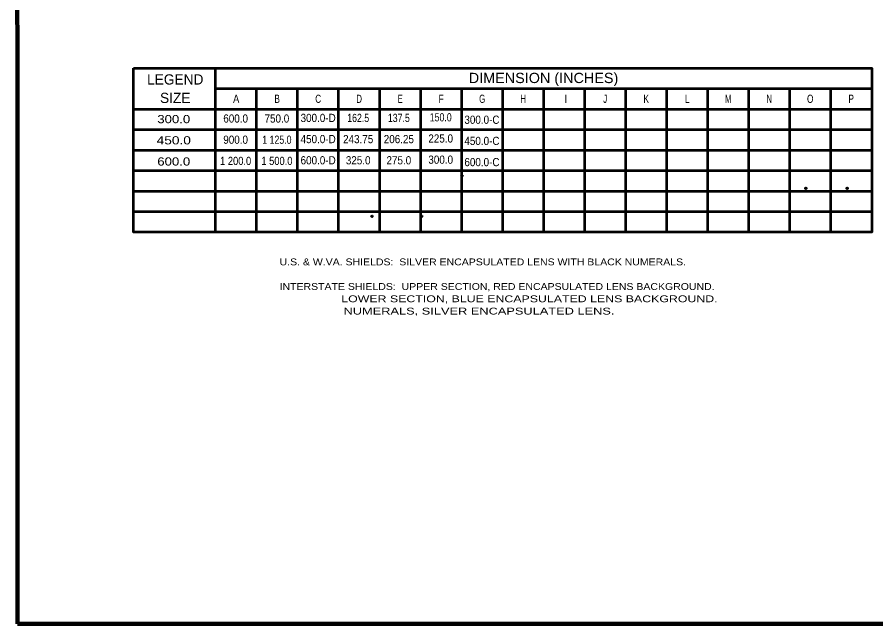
# Model space of a CAD drawing. Extents: x -96 to 760, y -448 to 96.
# Drawn here: x -38.6 to 338.4, y -436.4 to -170.2 of the extents above; entities that cross this region are included whole.
import ezdxf
from ezdxf.enums import TextEntityAlignment as Align

# ---------------------------------------------------------------- set-up
doc = ezdxf.new("R2010")
doc.units = 0
doc.header["$LTSCALE"] = 1.4
doc.header["$PDMODE"] = 32
doc.header["$PDSIZE"] = 0.7
doc.layers.add('1', color=7, linetype='Continuous', lineweight=40)

msp = doc.modelspace()

# ---------------------------------------------------------------- linework, layer by layer
at = {"layer": '1', "lineweight": 53}
for p, q in [((48.565, -264.488), (48.565, -192.488)), ((48.565, -201.488), (336.565, -201.488)), ((66.565, -264.488), (66.565, -201.488)), ((84.565, -264.488), (84.565, -201.488)), ((102.565, -264.488), (102.565, -201.488)), ((120.565, -264.488), (120.565, -201.488)), ((138.565, -264.488), (138.565, -201.488)), ((156.565, -264.488), (156.565, -201.488)), ((174.565, -264.488), (174.565, -201.488)), ((192.565, -264.488), (192.565, -201.488)), ((210.565, -264.488), (210.565, -201.488)), ((228.565, -264.488), (228.565, -201.488)), ((246.565, -264.488), (246.565, -201.488)), ((264.565, -264.488), (264.565, -201.488)), ((282.565, -264.488), (282.565, -201.488)), ((300.565, -264.488), (300.565, -201.488)), ((318.565, -264.488), (318.565, -201.488)), ((192.565, -210.488), (210.565, -210.488)), ((206.065, -210.488), (233.065, -210.488)), ((12.565, -219.488), (336.565, -219.488)), ((12.565, -228.488), (336.565, -228.488)), ((12.565, -237.488), (336.565, -237.488)), ((12.565, -246.488), (336.565, -246.488)), ((12.565, -255.488), (336.565, -255.488))]:
    msp.add_line(p, q, dxfattribs=at)
at = {"layer": '1', "lineweight": 158}
msp.add_line((753.127, -436.444), (-38.473, -436.444), dxfattribs=at)
msp.add_lwpolyline([(753.127, 89.656), (-38.573, 89.556), (-38.473, -436.444)], dxfattribs=at)
at = {"layer": '1', "lineweight": 53}
msp.add_lwpolyline([(12.565, -192.488), (336.565, -192.488), (336.565, -264.488), (12.565, -264.488)], close=True, dxfattribs=at)
for points in [[(12.565, -210.488), (48.565, -210.488), (66.565, -210.488), (84.565, -210.488), (102.565, -210.488), (120.565, -210.488), (138.565, -210.488), (156.565, -210.488), (174.565, -210.488), (197.065, -210.488)], [(228.565, -210.488), (246.565, -210.488), (264.565, -210.488), (282.565, -210.488), (300.565, -210.488), (318.565, -210.488), (336.565, -210.488)]]:
    msp.add_lwpolyline(points, dxfattribs=at)
at = {"layer": '1'}
for p in [(156.706, -239.912), (307.656, -245.336), (325.807, -245.336), (117.231, -257.607), (139.011, -257.607)]:
    msp.add_point(p, dxfattribs=at)

# ---------------------------------------------------------------- texts
for s, height, p in [('LEGEND', 4.5, (30.823, -199.738)), ('SIZE', 4.5, (30.823, -207.838)), ('I', 3.6, (202.228, -207.788))]:
    msp.add_text(s, height=height, dxfattribs=at).set_placement(p, align=Align.CENTER)
for s, height, width, p in [('DIMENSION (INCHES)', 4.5, 1.05, (192.511, -199.091)), ('A', 3.6, 0.85, (57.579, -207.788)), ('B', 3.6, 0.75, (75.579, -207.788)), ('C', 3.6, 0.75, (93.579, -207.788)), ('D', 3.6, 0.7, (111.579, -207.788)), ('E', 3.6, 0.7, (129.579, -207.788)), ('F', 3.6, 0.75, (147.579, -207.788)), ('G', 3.6, 0.7, (165.579, -207.788)), ('H', 3.6, 0.7, (183.579, -207.788)), ('J', 3.6, 0.7, (219.579, -207.788)), ('K', 3.6, 0.75, (237.579, -207.788)), ('L', 3.6, 0.75, (255.579, -207.788)), ('M', 3.6, 0.7, (273.579, -207.788)), ('N', 3.6, 0.7, (291.579, -207.788)), ('O', 3.6, 0.75, (309.579, -207.788)), ('P', 3.6, 0.75, (327.579, -207.788)), ('300.0', 3.6, 1.2, (30.17, -216.712)), ('600.0', 3.6, 0.9, (57.336, -216.446)), ('750.0', 3.6, 0.9, (75.447, -216.446)), ('300.0-D', 3.6, 0.9, (93.558, -216.179)), ('162.5', 3.6, 0.8, (111.136, -216.179)), ('137.5', 3.6, 0.8, (128.98, -216.179)), ('150.0', 3.6, 0.8, (147.357, -215.913)), ('300.0-C', 3.6, 0.9, (165.468, -216.978)), ('450.0', 3.6, 1.25, (30.17, -226.012)), ('900.0', 3.6, 0.9, (57.336, -225.746)), ('1 125.0', 3.6, 0.8, (75.447, -225.746)), ('450.0-D', 3.6, 0.9, (93.558, -225.479)), ('243.75', 3.6, 0.9, (111.136, -225.479)), ('206.25', 3.6, 0.9, (128.98, -225.479)), ('225.0', 3.6, 0.9, (147.357, -225.213)), ('450.0-C', 3.6, 0.9, (165.468, -226.278)), ('600.0', 3.6, 1.2, (30.17, -235.312)), ('1 200.0', 3.6, 0.85, (57.336, -235.046)), ('1 500.0', 3.6, 0.85, (75.447, -235.046)), ('600.0-D', 3.6, 0.9, (93.558, -234.779)), ('325.0', 3.6, 0.9, (111.136, -234.779)), ('275.0', 3.6, 0.9, (128.98, -234.779)), ('300.0', 3.6, 0.9, (147.357, -234.513)), ('600.0-C', 3.6, 0.9, (165.468, -235.578))]:
    msp.add_text(s, height=height, dxfattribs=dict(at, width=width)).set_placement(p, align=Align.CENTER)
for s, width, p in [('U.S. & W.VA. SHIELDS:  SILVER ENCAPSULATED LENS WITH BLACK NUMERALS.', 1.15, (76.624, -279.087)), ('INTERSTATE SHIELDS:  UPPER SECTION, RED ENCAPSULATED LENS BACKGROUND.', 1.15, (76.624, -289.887)), ('                  LOWER SECTION, BLUE ENCAPSULATED LENS BACKGROUND.', 1.35, (76.624, -295.287)), ('                  NUMERALS, SILVER ENCAPSULATED LENS.', 1.4, (76.624, -300.687))]:
    msp.add_text(s, height=3, dxfattribs=dict(at, width=width)).set_placement(p)

doc.saveas('drawing.dxf')
